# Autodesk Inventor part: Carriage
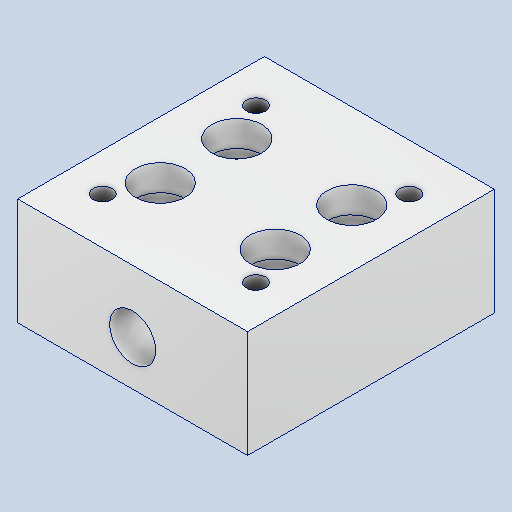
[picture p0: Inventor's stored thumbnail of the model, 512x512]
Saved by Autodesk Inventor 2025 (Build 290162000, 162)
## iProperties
Created: 2021-07
Part Number: Carriage
Material: Alluminio 6061
Document SubType Name: Modeling
Designer: Ryzen5700u
Density: 2.7 g/cm^3
Appearance: Default
Author: Ryzen5700u
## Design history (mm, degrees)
feature "Solido1"
node "Solido2"
